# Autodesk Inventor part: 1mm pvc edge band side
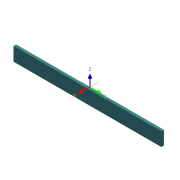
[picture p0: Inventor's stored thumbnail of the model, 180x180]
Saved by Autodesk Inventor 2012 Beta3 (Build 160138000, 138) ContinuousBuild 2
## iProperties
Created: 2011-02
Part Number: 1mm pvc edge band side
Material: Default
Document SubType Name: Modeling
Designer: Beta-8540w
Density: 1 g/cm^3
drwr_height: 5.000 in
Author: Beta-8540w
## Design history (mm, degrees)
sketch "Sketch1"
  geometry: L1 (-75.2, 7.937)-(75.2, 7.937); L2 (75.2, 7.937)-(75.2, -7.938); L3 (75.2, -7.938)-(-75.2, -7.938); L4 (-75.2, -7.938)-(-75.2, 7.937); 3 further points
  constraints: 8 end point, 2 midpoint, 2 parallel, 1 horizontal, 1 horizontal alignment, 1 perpendicular, 1 vertical alignment
  dimensions: "d0" = 150.4 distance of L1.start L1.end (= drawer_height - 2 x d2); "d1" = 15.875 distance of L3.end L1.start
extrude "Extrusion1" new body sketch "Sketch1" distance "d2" = 1 (= edge_band_thickness); taper "d3" = 0 deg
body "Solid1"
other parameters: "d4" = 0, "d5" = 0, "d6" = 0, "d7" = 0, "d8" = 0, "d9" = 0, "drwr_height" = 127 [user parameter], "drawer_height" = 152.4, "edge_band_thickness" = 1
